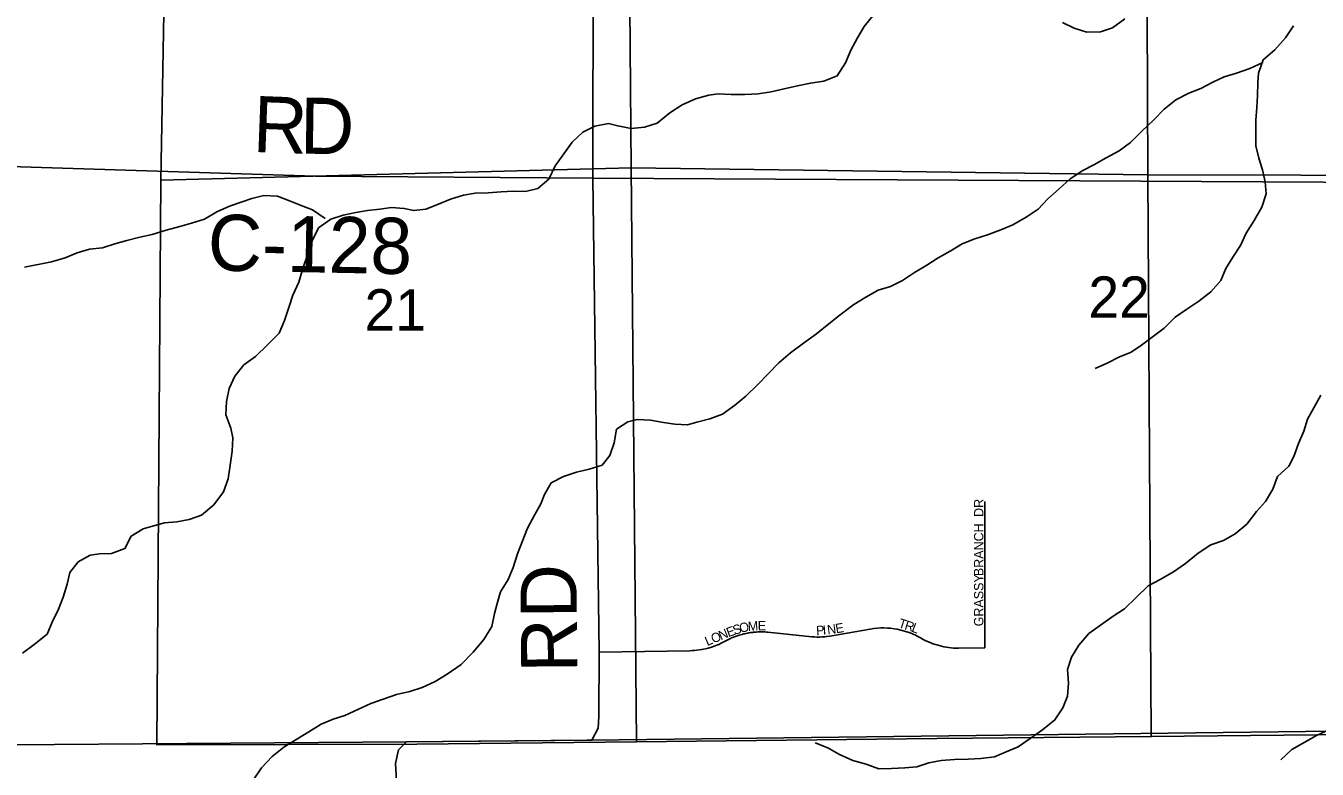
# Model space of a CAD drawing. Extents: x 1985906 to 2277390, y 930619 to 1324581.
# Drawn here: x 2115559 to 2122467, y 1165893 to 1169867 of the extents above; entities that cross this region are included whole.
import ezdxf

# ---------------------------------------------------------------- set-up
doc = ezdxf.new("R2010")
doc.units = 0
for name, color, linetype in [('GM_X_County_Road', 7, 'Continuous'), ('GM_X_County_Road_Text', 7, 'Continuous'), ('GM_X_Minor_River', 7, 'Continuous'), ('GM_X_Section', 7, 'Continuous'), ('GM_X_Section_Text', 7, 'Continuous'), ('GM_X_Township', 7, 'Continuous'), ('GM_X_Township_Subdivision', 7, 'Continuous'), ('GM_X_Township_Subdivision_Text', 7, 'Continuous')]:
    doc.layers.add(name, color=color, linetype=linetype)

msp = doc.modelspace()

# ---------------------------------------------------------------- linework, layer by layer
at = {"layer": 'GM_X_County_Road'}
for points in [[(2118560.5, 1166047.6), (2118586.8, 1166047.8), (2118620.6, 1166112.6), (2118623.5, 1166174.5), (2118626.1, 1166518.4), (2118591.2, 1169053.3), (2118594.5, 1170214.3), (2118606.5, 1174543.1), (2118608.8, 1176008.8), (2118650, 1179910.2)], [(2113371.6, 1168723.2), (2113414.9, 1168817.1), (2113590.9, 1168968.2), (2113749.7, 1169088.7), (2113793.7, 1169111.7), (2113843.4, 1169117.4), (2113964, 1169125.1), (2115416, 1169116.9), (2117106.6, 1169063.1), (2118591.2, 1169053.3)], [(2118591.2, 1169053.3), (2123801.3, 1169024), (2125876.3, 1169024.6), (2126468.2, 1169024.7)], [(2117515.4, 1163056.1), (2117521, 1163983.8), (2117544.8, 1165766.2), (2117536.2, 1165924.3), (2117553.3, 1165997.1), (2117595.5, 1166039.3), (2118560.5, 1166047.6)]]:
    msp.add_lwpolyline(points, dxfattribs=at)
at = {"layer": 'GM_X_Minor_River'}
for points in [[(2120097, 1169930), (2120043.1, 1169863.5), (2120007.3, 1169803.1), (2119971.5, 1169736.8), (2119943.7, 1169670.4), (2119899.8, 1169599.9), (2119827.7, 1169571.6), (2119755.6, 1169561.3), (2119687.4, 1169547), (2119615.2, 1169530.7), (2119545.1, 1169514.4), (2119476.9, 1169504.1), (2119404.7, 1169499.8), (2119332.4, 1169499.6), (2119262.2, 1169503.4), (2119212.1, 1169497.2), (2119141.9, 1169476.9), (2119069.8, 1169444.5), (2119003.8, 1169402.1), (2118935.8, 1169347.6), (2118867.7, 1169325.3), (2118797.5, 1169319.1), (2118725.2, 1169332.8), (2118675, 1169344.7), (2118602.8, 1169330.4), (2118538.8, 1169298.1), (2118480.8, 1169245.7), (2118436.9, 1169183.2), (2118391.1, 1169118.8), (2118357.3, 1169048.4), (2118297.3, 1168998), (2118231.2, 1168981.7), (2118165, 1168983.5), (2118100.8, 1168979.3), (2118032.6, 1168975), (2117962.3, 1168972.8), (2117900.2, 1168962.5), (2117830.1, 1168940.2), (2117758, 1168909.8), (2117697.9, 1168887.5), (2117633.7, 1168879.3), (2117583.5, 1168891.2), (2117515.2, 1168896.9), (2117453.1, 1168886.7), (2117386.9, 1168880.4), (2117324.7, 1168870.2), (2117256.6, 1168855.9), (2117190.4, 1168833.6), (2117124.4, 1168787.2), (2117090.6, 1168718.8), (2117064.9, 1168642.4), (2117041.1, 1168570), (2117019.4, 1168497.6), (2116987.6, 1168427.2), (2116965.8, 1168360.9), (2116942.1, 1168292.5), (2116914.3, 1168224.2), (2116852.4, 1168161.7), (2116788.4, 1168099.2), (2116724.4, 1168054.8), (2116676.6, 1167994.4), (2116646.8, 1167928.1), (2116633, 1167859.7), (2116629.3, 1167787.4)], [(2121437.5, 1169904.4), (2121371.5, 1169856), (2121307.4, 1169835.7), (2121235.2, 1169833.5), (2121166.8, 1169855.3), (2121104.5, 1169885.2)], [(2121279.8, 1168035.6), (2121346.1, 1168065.4), (2121408.5, 1168097.1), (2121468.7, 1168120.9), (2121519, 1168154.8), (2121647.9, 1168250.5), (2121706.3, 1168310.4), (2121768.7, 1168352.3), (2121833.1, 1168396.1), (2121897.5, 1168446), (2121952, 1168506), (2121978.4, 1168570.1), (2122014.8, 1168630.2), (2122057.2, 1168692.2), (2122087.6, 1168758.3), (2122130.1, 1168826.4), (2122170.5, 1168898.5), (2122192.9, 1168968.6), (2122189.2, 1169032.9), (2122173.5, 1169097.3), (2122153.8, 1169159.7), (2122138, 1169226), (2122138.7, 1169362.6), (2122143.1, 1169430.9), (2122147.4, 1169495.1), (2122149.7, 1169563.4), (2122152, 1169613.6), (2122178.4, 1169685.8), (2122240.9, 1169739.7), (2122297.3, 1169803.7), (2122339.8, 1169867.7)], [(2122175, 1169672), (2122106.9, 1169639.6), (2122034.8, 1169615.3), (2121968.6, 1169595), (2121908.6, 1169566.7), (2121844.5, 1169532.3), (2121780.4, 1169508), (2121710.3, 1169471.6), (2121648.4, 1169421.2), (2121592.4, 1169364.8), (2121528.5, 1169304.3), (2121468.6, 1169243.8), (2121406.6, 1169199.4), (2121338.5, 1169161.1), (2121272.5, 1169124.7), (2121212.4, 1169094.3), (2121144.4, 1169049.9), (2121086.5, 1168995.5), (2121026.5, 1168943.1), (2120974.6, 1168886.7), (2120910.6, 1168844.3), (2120838.5, 1168803.9), (2120774.4, 1168777.6), (2120702.3, 1168749.2), (2120636.2, 1168728.9), (2120568.1, 1168702.6), (2120504.1, 1168662.2), (2120440, 1168627.8), (2120378, 1168587.4), (2120311.9, 1168549.1), (2120247.9, 1168506.7), (2120183.9, 1168474.3), (2120117.7, 1168454), (2120051.7, 1168417.6), (2119987.7, 1168377.2), (2119915.7, 1168322.8), (2119853.7, 1168274.4), (2119787.7, 1168219.9), (2119719.7, 1168171.5), (2119649.7, 1168119.1), (2119587.8, 1168066.6), (2119529.8, 1168006.2), (2119473.9, 1167949.8), (2119410, 1167887.3), (2119350, 1167836.9), (2119286, 1167790.5), (2119217.9, 1167766.1), (2119147.8, 1167747.8), (2119097.7, 1167733.6), (2119031.4, 1167737.4), (2118969.2, 1167747.2), (2118900.9, 1167759), (2118828.6, 1167762.8), (2118778.5, 1167750.6), (2118718.5, 1167710.2), (2118706.8, 1167637.9), (2118683, 1167569.5), (2118641.1, 1167519.2), (2118573, 1167496.9), (2118504.9, 1167480.6), (2118434.7, 1167458.2), (2118368.7, 1167423.9), (2118332.8, 1167361.5), (2118313, 1167311.2), (2118279.2, 1167250.9), (2118243.4, 1167182.5), (2118213.6, 1167108.1), (2118189.8, 1167043.7), (2118166.1, 1166971.3), (2118138.3, 1166907), (2118098.4, 1166840.6), (2118080.7, 1166778.3), (2118066.8, 1166726), (2118051.1, 1166655.7), (2118009.3, 1166587.3), (2117951.4, 1166518.8), (2117887.5, 1166452.3), (2117813.5, 1166401.9), (2117749.5, 1166361.5), (2117679.4, 1166329.1), (2117613.3, 1166308.8), (2117541.1, 1166292.5), (2117471, 1166268.2), (2117404.9, 1166243.8), (2117334.8, 1166211.5), (2117264.7, 1166181.1), (2117202.6, 1166160.8), (2117138.5, 1166134.5), (2117072.5, 1166092.1), (2117008.4, 1166053.7), (2116938.4, 1166011.3), (2116876.4, 1165960.9), (2116820.5, 1165900.5), (2116770.7, 1165830)], [(2117160.3, 1168837.5), (2117091.9, 1168883.5), (2117031.6, 1168907.3), (2116969.3, 1168931.2), (2116904.9, 1168957.1), (2116832.7, 1168960.9), (2116768.6, 1168944.6), (2116716.5, 1168926.4), (2116648.3, 1168904), (2116580.3, 1168873.7), (2116514.2, 1168833.3), (2116446.1, 1168813), (2116382, 1168794.7), (2116309.8, 1168774.4), (2116235.7, 1168752), (2116169.5, 1168737.7), (2116099.4, 1168719.4), (2116035.2, 1168701.1), (2115969.1, 1168680.8), (2115898.9, 1168672.6), (2115832.8, 1168654.2), (2115768.7, 1168627.9), (2115696.6, 1168605.6), (2115552.2, 1168577)], [(2119781.8, 1166033.2), (2119849.8, 1166006.7), (2119911.8, 1165972.3), (2119981.9, 1165939.7), (2120054, 1165919.3), (2120122, 1165894.8), (2120190.2, 1165896.4), (2120260.5, 1165900.1), (2120324.7, 1165905.8), (2120388.9, 1165927.5), (2120455.2, 1165939.2), (2120527.4, 1165944.8), (2120599.6, 1165946.4), (2120667.8, 1165950.1), (2120740.1, 1165959.7), (2120802.4, 1165985.5), (2120866.7, 1166013.3), (2120931.1, 1166057.1), (2120997.5, 1166102.9), (2121063.9, 1166156.8), (2121106.4, 1166220.8), (2121130.7, 1166283), (2121137.1, 1166353.2), (2121131.5, 1166425.6), (2121151.8, 1166491.7), (2121192.3, 1166555.8), (2121244.7, 1166617.8), (2121307.1, 1166663.6), (2121375.5, 1166711.4), (2121435.9, 1166751.3), (2121498.4, 1166811.2), (2121562.9, 1166873.1), (2121627.2, 1166906.9), (2121697.6, 1166948.7), (2121762, 1166992.6), (2121830.5, 1167048.4), (2121896.9, 1167092.2), (2121965.2, 1167116), (2122027.5, 1167151.8), (2122089.9, 1167203.7), (2122142.4, 1167271.7), (2122190.8, 1167323.6), (2122229.2, 1167389.7), (2122253.6, 1167457.9), (2122314.1, 1167513.8), (2122342.4, 1167565.8), (2122366.8, 1167634), (2122395.2, 1167700.1), (2122415.6, 1167764.3), (2122448, 1167824.4), (2122486.4, 1167892.4)], [(2116629.3, 1167787.4), (2116655.7, 1167717.2), (2116666, 1167665.1), (2116662.3, 1167592.8), (2116652.6, 1167518.4), (2116640.9, 1167446.1), (2116617.2, 1167375.7), (2116565.3, 1167307.3), (2116499.3, 1167250.8), (2116433.2, 1167228.5), (2116367.1, 1167216.2), (2116300.9, 1167210), (2116236.8, 1167191.7), (2116186.6, 1167177.5), (2116122.6, 1167139.1), (2116088.8, 1167072.7), (2116016.7, 1167046.3), (2115952.5, 1167044.1), (2115902.4, 1167037.9), (2115838.3, 1167001.6), (2115794.4, 1166945.2), (2115780.7, 1166882.9), (2115758.9, 1166812.5), (2115733.1, 1166748.2), (2115699.3, 1166679.8), (2115673.5, 1166615.4), (2115603.5, 1166559), (2115541.5, 1166512.6)], [(2122272.2, 1165943.3), (2122330.7, 1165999.3), (2122397, 1166035.1), (2122463.4, 1166072.9), (2122525.7, 1166102.6)]]:
    msp.add_lwpolyline(points, dxfattribs=at)
at = {"layer": 'GM_X_Section'}
for points in [[(2116329.9, 1171718.9), (2118774.8, 1171689.5), (2118797.6, 1169108.6), (2116281, 1169042.8)], [(2118774.8, 1171689.5), (2121549.7, 1171656.3), (2121561.1, 1169070), (2118797.6, 1169108.6)], [(2121549.7, 1171656.3), (2123960.3, 1171627.4), (2124015.2, 1169066), (2121561.1, 1169070)], [(2116281, 1169042.8), (2118797.6, 1169108.6), (2118824.7, 1166039.9), (2117650.7, 1166026.6), (2116260.4, 1166023)], [(2118797.6, 1169108.6), (2121561.1, 1169070), (2121579.2, 1166067.2), (2120432.9, 1166057.2), (2118824.7, 1166039.9)], [(2121561.1, 1169070), (2124015.2, 1169066), (2124078.8, 1166101.7), (2123173.5, 1166084), (2121579.2, 1166067.2)]]:
    msp.add_lwpolyline(points, close=True, dxfattribs=at)
at = {"layer": 'GM_X_Township'}
for points in [[(2139611.5, 1172078.9), (2139644.7, 1169748.4), (2139656.8, 1167688.3), (2139668.5, 1166493.7), (2139667, 1166451.3), (2138508.5, 1166420.6), (2137115, 1166387.6), (2131684.3, 1166258.8), (2126498.2, 1166145.1), (2123749.2, 1166110.6), (2123139.1, 1166103.1), (2118586.8, 1166047.8), (2117595.5, 1166039.3), (2113358.2, 1166007.9), (2113371.6, 1168723.2), (2113398.8, 1174226.6)], [(2113093.1, 1145116.7), (2113139.2, 1149689.6), (2113152.8, 1150701.9), (2113157.3, 1151039.7), (2113184.2, 1154330.1), (2113217.3, 1157737.8), (2113243.3, 1159266.8), (2113263, 1160423.4), (2113290.5, 1162037.2), (2113339.2, 1164894), (2113356.1, 1165889.3), (2113358.2, 1166007.9), (2117595.5, 1166039.3), (2118586.8, 1166047.8), (2123139.1, 1166103.1), (2123749.2, 1166110.6), (2126498.2, 1166145.1), (2131684.3, 1166258.8), (2137115, 1166387.6), (2138508.5, 1166420.6), (2139667, 1166451.3), (2139679.7, 1165170.7), (2139697.8, 1163007), (2139715.7, 1160875.4)]]:
    msp.add_lwpolyline(points, dxfattribs=at)
at = {"layer": 'GM_X_Township_Subdivision'}
for points in [[(2120688.7, 1166542.7), (2120688.9, 1167324)], [(2118626.1, 1166518.4), (2119110.7, 1166526.8), (2119123.3, 1166527.2), (2119135.2, 1166527.9), (2119147.2, 1166529), (2119161.2, 1166530.8), (2119173.3, 1166532.7), (2119183.3, 1166534.6), (2119194.1, 1166536.9), (2119201.1, 1166538.5), (2119208.1, 1166540.4), (2119214.7, 1166542.2), (2119221.5, 1166544.2), (2119231.7, 1166547.5), (2119241.7, 1166551), (2119254.5, 1166555.9), (2119265.6, 1166560.6), (2119277.7, 1166566.1), (2119288.6, 1166571.6), (2119299.2, 1166577.3), (2119310.1, 1166583.1), (2119321.6, 1166588.7), (2119328.6, 1166592), (2119334.6, 1166594.7), (2119340.8, 1166597.3), (2119348.7, 1166600.4), (2119355.7, 1166603.1), (2119358.6, 1166604.1), (2119363.3, 1166605.7), (2119375.6, 1166609.7), (2119382.4, 1166611.8), (2119389.9, 1166613.8), (2119398.2, 1166616), (2119404.4, 1166617.4), (2119411.6, 1166619), (2119420.4, 1166620.7), (2119426, 1166621.7), (2119436.3, 1166623.4), (2119443.2, 1166624.3), (2119446.7, 1166624.7), (2119451.2, 1166625.2), (2119458.4, 1166625.9), (2119465.5, 1166626.5), (2119474.1, 1166627), (2119482.2, 1166627.3), (2119497.7, 1166627.4), (2119504.9, 1166627.3), (2119511.8, 1166627), (2119520.7, 1166626.5), (2119528.2, 1166625.9), (2119764, 1166601.1), (2119777.5, 1166600.2), (2119790.6, 1166599.8), (2119798.4, 1166599.7), (2119805.4, 1166599.8), (2119817.6, 1166600.3), (2119826.4, 1166600.8), (2119832.9, 1166601.3), (2119840.2, 1166602.1), (2119844.8, 1166602.6), (2119859.7, 1166604.7), (2119870.9, 1166606.7), (2120074.9, 1166642.6), (2120094.5, 1166645.6), (2120113.4, 1166647.5), (2120131.8, 1166648.5), (2120148.9, 1166648.7), (2120167.9, 1166648), (2120184.2, 1166646.7), (2120203.6, 1166644.3), (2120219.5, 1166641.6), (2120259.1, 1166631.9), (2120289.4, 1166621.5), (2120317.9, 1166609.2), (2120334.1, 1166600.9), (2120344.8, 1166594.9), (2120358.5, 1166587.3), (2120369.4, 1166581.7), (2120382.2, 1166575.7), (2120396.1, 1166569.7), (2120407.1, 1166565.4), (2120417, 1166561.9), (2120431.6, 1166557.2), (2120444.4, 1166553.6), (2120457.4, 1166550.4), (2120468.8, 1166547.9), (2120483.1, 1166545.4), (2120494.3, 1166543.7), (2120508.3, 1166542.1), (2120521, 1166541.1), (2120532.9, 1166540.5), (2120548.7, 1166540.3), (2120688.7, 1166542.7)]]:
    msp.add_lwpolyline(points, dxfattribs=at)

# ---------------------------------------------------------------- texts
at = {"layer": 'GM_X_County_Road_Text'}
for s, rotation, p in [('R', 357.8763, (2116770.4, 1169193.6)), ('D', 359.18195, (2117024, 1169184.3)), ('C-128', 358.90193, (2116530.3, 1168560.2)), ('RD', 90.47726, (2118509, 1166411.1))]:
    msp.add_text(s, height=300, rotation=rotation, dxfattribs=at).set_placement(p)
at = {"layer": 'GM_X_Section_Text'}
for s, p in [('22', (2121242.7, 1168306.6)), ('21', (2117370.7, 1168238.4))]:
    msp.add_text(s, height=221, rotation=0.00001, dxfattribs=at).set_placement(p)
at = {"layer": 'GM_X_Township_Subdivision_Text'}
for s, rotation, p in [('DR', 90, (2120681.1, 1167242)), ('BRANCH', 90, (2120681.1, 1166925.2)), ('GRASSY', 90, (2120681.1, 1166656.8)), ('O', 13.41072, (2119382, 1166621.5)), ('M', 4.2115, (2119422.7, 1166631.3)), ('E', 0.43716, (2119474.5, 1166635.2)), ('E', 9.41992, (2119893.9, 1166619.4)), ('T', 342.5759, (2120222.5, 1166652.6)), ('R', 341.87227, (2120255.9, 1166642.1)), ('O', 22.89726, (2119236.5, 1166564.8)), ('N', 22.49545, (2119276.9, 1166581.9)), ('E', 20.08115, (2119317.1, 1166598.5)), ('S', 18.74596, (2119349.8, 1166610.5)), ('P', 3.71865, (2119788, 1166609)), ('I', 4.20677, (2119823.5, 1166611.4)), ('N', 7.69803, (2119848.7, 1166613.3)), ('L', 339.07625, (2120293, 1166630)), ('L', 22.89726, (2119204, 1166551.1))]:
    msp.add_text(s, height=50, rotation=rotation, dxfattribs=at).set_placement(p)

doc.saveas('drawing.dxf')
